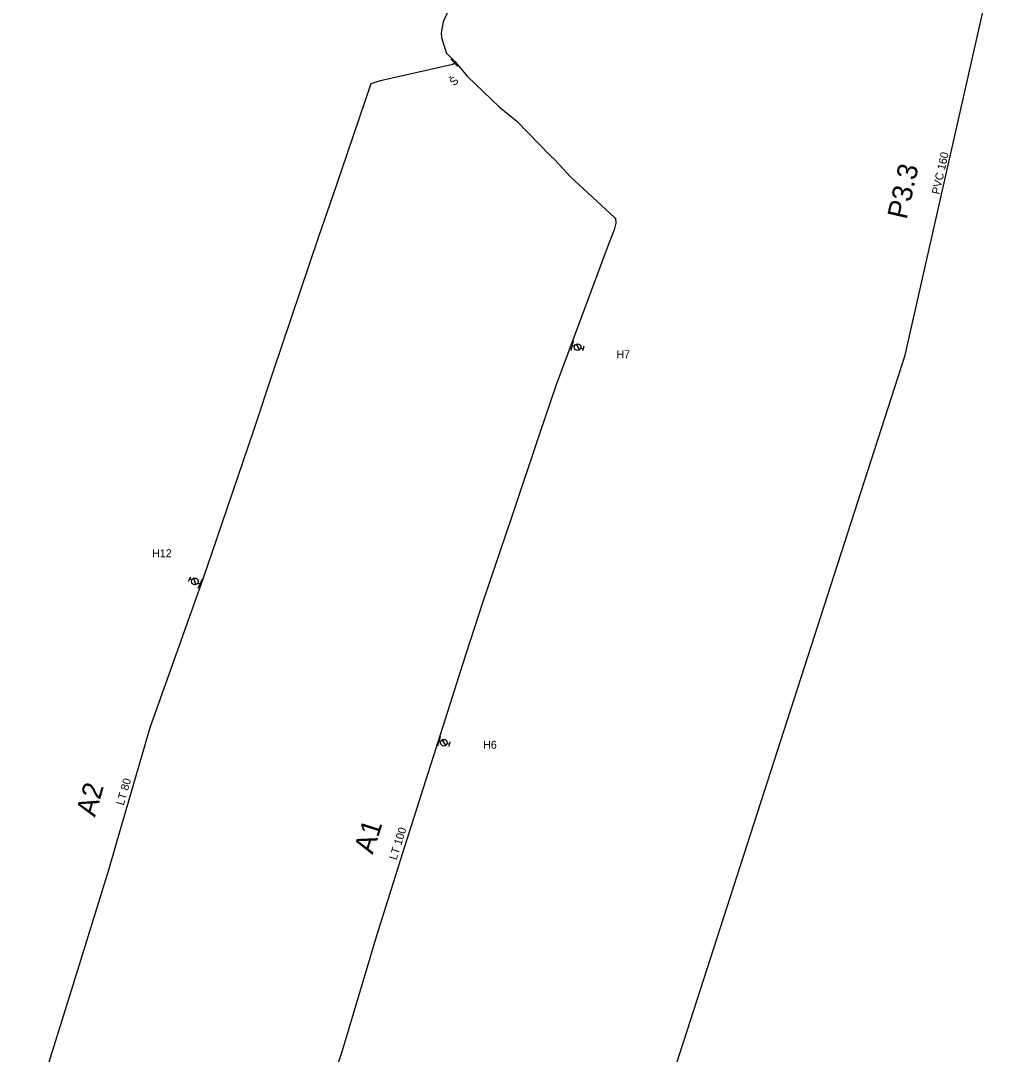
# Model space of a CAD drawing. Extents: x -574447 to -573745, y -1188179 to -1187219.
# Drawn here: x -573987.1 to -573745, y -1187920.3 to -1187661.9 of the extents above; entities that cross this region are included whole.
import ezdxf

# ---------------------------------------------------------------- set-up
doc = ezdxf.new("R2010")
doc.units = 0
for name, color, linetype in [('Vrstva 1', 7, 'Continuous'), ('Vrstva 15', 7, 'Continuous'), ('Vrstva 19', 7, 'Continuous'), ('Vrstva 25', 7, 'Continuous'), ('Vrstva 28', 7, 'Continuous'), ('Vrstva 29', 7, 'Continuous'), ('Vrstva 35', 7, 'Continuous')]:
    doc.layers.add(name, color=color, linetype=linetype)

# ---------------------------------------------------------------- blocks, each defined once
blk = doc.blocks.new('160')
at = {"layer": 'Vrstva 1'}
blk.add_circle((0, 0), 0.0458, dxfattribs=at)
blk = doc.blocks.new('147')
at = {"layer": 'Vrstva 1'}
blk.add_line((0, 1.27), (0, -1.27), dxfattribs=at)
blk = doc.blocks.new('133')
at = {"layer": 'Vrstva 1'}
for p, q in [((0.28, 0), (0, 0)), ((0.54, 0.58), (1.7, -0.58)), ((1.94, 0), (2.52, 0)), ((2.52, 0.58), (2.52, -0.58))]:
    blk.add_line(p, q, dxfattribs=at)
blk.add_circle((1.105, 0.003), 0.825, dxfattribs=at)
blk = doc.blocks.new('150')
at = {"layer": 'Vrstva 1'}
blk.add_line((0, 1.27), (0, -1.27), dxfattribs=at)

msp = doc.modelspace()

# ---------------------------------------------------------------- linework, layer by layer
at = {"layer": 'Vrstva 15'}
msp.add_line((-573878.585, -1187672.401), (-573878.361, -1187672.175), dxfattribs=at)
for points in [[(-573879.671, -1187658.332), (-573881.35, -1187662.21), (-573881.87, -1187664.95), (-573881.84, -1187666.09), (-573881.2, -1187668.04), (-573880.56, -1187669.99), (-573878.361, -1187672.175)], [(-573987.085, -1187945.205), (-573973.536, -1187901.624), (-573965.018, -1187874.191), (-573963.068, -1187867.466), (-573954.7, -1187838.611), (-573941.356, -1187801.149), (-573938.047, -1187791.432), (-573928.782, -1187764.229), (-573923.893, -1187749.662), (-573912.469, -1187715.852), (-573908.18, -1187703.312), (-573899.39, -1187677.61), (-573897.1, -1187676.87), (-573894.105, -1187676.193), (-573878.95, -1187672.77), (-573878.585, -1187672.401)], [(-573878.361, -1187672.175), (-573875.27, -1187675.81), (-573867.39, -1187683.44), (-573862.942, -1187687.04), (-573854.577, -1187695.589), (-573853.48, -1187696.71), (-573849.51, -1187700.91), (-573838.51, -1187711.1), (-573838.28, -1187711.29), (-573838.15, -1187712.5), (-573838.63, -1187714.17), (-573839.89, -1187717.36), (-573853.13, -1187752.93), (-573857.172, -1187764.942), (-573864.214, -1187785.872), (-573871.67, -1187807.67), (-573876.61, -1187823.13), (-573878.535, -1187829.177), (-573891.106, -1187868.668), (-573898.1, -1187890.69), (-573906.65, -1187919.44), (-573909.867, -1187929.103)]]:
    msp.add_lwpolyline(points, dxfattribs=at)
at = {"layer": 'Vrstva 19'}
msp.add_lwpolyline([(-573776.7, -1187395.74), (-573776.433, -1187397.089), (-573756.58, -1187497.42), (-573746.79, -1187550.13), (-573745, -1187653.04), (-573765.99, -1187745.82), (-573827.995, -1187937.981), (-573851.222, -1188009.966), (-573853.24, -1188016.22), (-573855.495, -1188023.056)], dxfattribs=at)
at = {"layer": 'Vrstva 25'}
for p, q in [((-573849.457, -1187743.063), (-573848.821, -1187743.216)), ((-573941.942, -1187802.794), (-573942.486, -1187802.561)), ((-573882.624, -1187842.023), (-573882.275, -1187842.109))]:
    msp.add_line(p, q, dxfattribs=at)

# ---------------------------------------------------------------- block references
for name, p, xscale, yscale, rotation in [('150', (-573849.139, -1187743.14), 1.0009847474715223, 1.0009847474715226, -14.22432628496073), ('133', (-573848.821, -1187743.216), 1.0009847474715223, 1.0009847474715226, -14.22432628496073), ('133', (-573942.486, -1187802.561), 1.022584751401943, 1.022584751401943, 154.18102569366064), ('150', (-573942.214, -1187802.677), 1.0198568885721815, 1.0198568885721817, -26.39398240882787), ('150', (-573882.45, -1187842.066), 0.999999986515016, 0.9999999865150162, -15.000000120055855), ('133', (-573882.275, -1187842.109), 0.999999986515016, 0.9999999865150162, -15.000000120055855)]:
    msp.add_blockref(name, p, dxfattribs=dict(at, xscale=xscale, yscale=yscale, rotation=rotation))
at = {"layer": 'Vrstva 29'}
for name, p, xscale, yscale, rotation in [('147', (-573878.585, -1187672.401), 0.9999999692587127, 0.9999999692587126, -136.00000080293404), ('160', (-573878.361, -1187672.175), 0.9999999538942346, 0.9999999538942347, 177.9999999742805)]:
    msp.add_blockref(name, p, dxfattribs=dict(at, xscale=xscale, yscale=yscale, rotation=rotation))

# ---------------------------------------------------------------- texts
at = {"layer": 'Vrstva 25'}
for s, p in [('H7', (-573838.061, -1187746.276)), ('H12', (-573954.206, -1187796.021)), ('H6', (-573871.395, -1187843.909))]:
    msp.add_text(s, height=2, dxfattribs=at).set_placement(p)
at = {"layer": 'Vrstva 28'}
msp.add_text('Š', height=2, rotation=44.79, dxfattribs=at).set_placement((-573878.616, -1187678.327))
at = {"layer": 'Vrstva 35'}
for s, height, rotation, p in [('PVC 160', 2, 77.25, (-573757.265, -1187705.443)), ('P3.3', 5, 77.25, (-573765.457, -1187711.753)), ('LT 80', 2, 73.83, (-573961.314, -1187858.191)), ('A2', 5, 73.83, (-573968.514, -1187861.126)), ('A1', 5, 72.34, (-573899.027, -1187870.465)), ('LT 100', 2, 72.34, (-573893.067, -1187871.857))]:
    msp.add_text(s, height=height, rotation=rotation, dxfattribs=at).set_placement(p)

doc.saveas('drawing.dxf')
